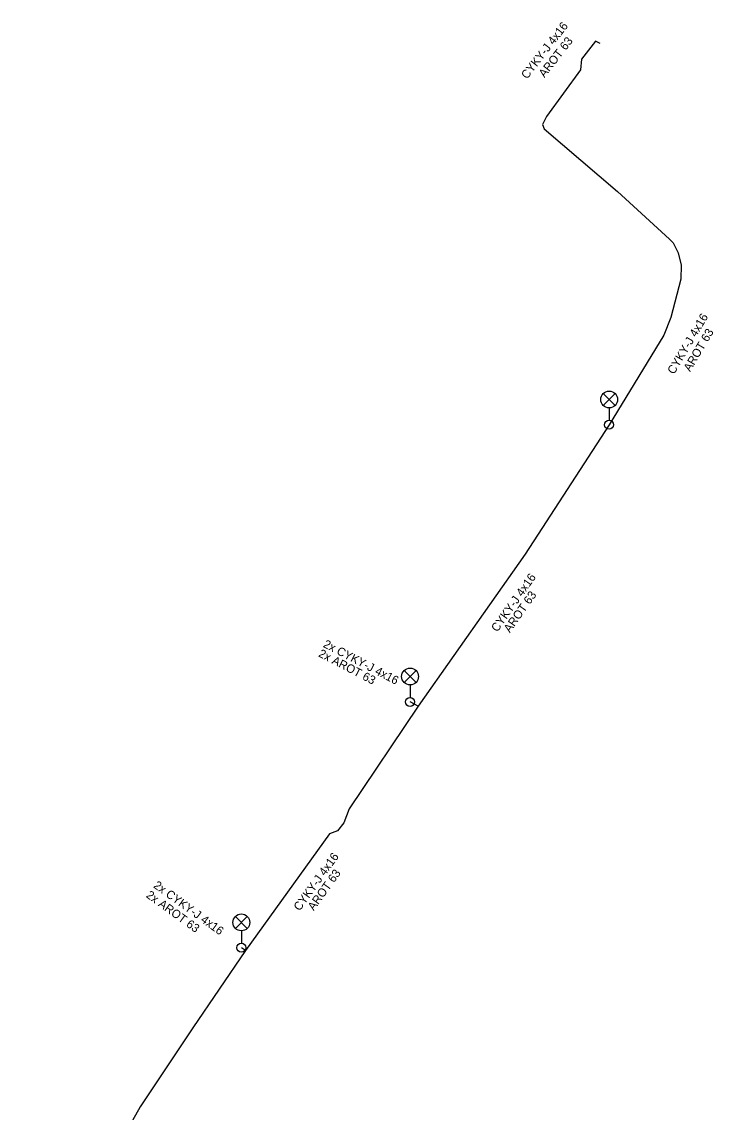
# Model space of a CAD drawing. Extents: x -600499 to -600324, y -1203856 to -1203661.
# Drawn here: x -600385.3 to -600323.8, y -1203757.5 to -1203660.6 of the extents above; entities that cross this region are included whole.
import ezdxf

# ---------------------------------------------------------------- set-up
doc = ezdxf.new("R2010")
doc.units = 0
for name, color, linetype in [('CIZÍ_PODZEM', 7, 'Continuous'), ('Default', 7, 'Continuous'), ('Vrstva 13', 7, 'Continuous'), ('Vrstva 5', 7, 'Continuous'), ('Vrstva 6', 7, 'Continuous'), ('ZP_EON', 7, 'Continuous')]:
    doc.layers.add(name, color=color, linetype=linetype)

# ---------------------------------------------------------------- blocks, each defined once
blk = doc.blocks.new('6.560')
at = {"layer": 'ZP_EON'}
for p, q in [((-0.53, 1.72), (0.53, 2.78)), ((-0.53, 2.78), (0.53, 1.72)), ((0, 1.5), (0, 0.4))]:
    blk.add_line(p, q, dxfattribs=at)
for centre, radius in [((0, 2.25), 0.75), ((0, 0), 0.4)]:
    blk.add_circle(centre, radius, dxfattribs=at)

msp = doc.modelspace()

# ---------------------------------------------------------------- linework, layer by layer
at = {"layer": 'Vrstva 13'}
for p, q in [((-600350.09, -1203721.39), (-600350.8, -1203721.02)), ((-600365.44, -1203743.11), (-600365.8, -1203742.86))]:
    msp.add_line(p, q, dxfattribs=at)
for points in [[(-600333.91, -1203662.54), (-600334.31, -1203662.32), (-600335.56, -1203663.93), (-600335.66, -1203664.87), (-600338.68, -1203669.03), (-600339.03, -1203669.74), (-600338.89, -1203670.11), (-600332.36, -1203675.7), (-600327.72, -1203679.92), (-600327.42, -1203680.26), (-600326.96, -1203681.14), (-600326.7, -1203682.24), (-600326.74, -1203683.47), (-600327.61, -1203686.88), (-600328.25, -1203688.44), (-600333.1, -1203696.41)], [(-600333.1, -1203696.41), (-600340.56, -1203707.89), (-600350.09, -1203721.39)], [(-600350.09, -1203721.39), (-600356.21, -1203730.52), (-600356.7, -1203731.78), (-600357.24, -1203732.48), (-600357.96, -1203732.75), (-600365.44, -1203743.11)], [(-600365.44, -1203743.11), (-600370.1, -1203749.97), (-600374.79, -1203756.99), (-600385.32, -1203775.71)]]:
    msp.add_lwpolyline(points, dxfattribs=at)
at = {"layer": 'Vrstva 5'}
for p, q in [((-600350.09, -1203721.39), (-600350.8, -1203721.02)), ((-600365.44, -1203743.11), (-600365.8, -1203742.86))]:
    msp.add_line(p, q, dxfattribs=at)
for points in [[(-600333.91, -1203662.54), (-600334.31, -1203662.32), (-600335.56, -1203663.93), (-600335.66, -1203664.87), (-600338.68, -1203669.03), (-600339.03, -1203669.74), (-600338.89, -1203670.11), (-600332.36, -1203675.7), (-600327.72, -1203679.92), (-600327.42, -1203680.26), (-600326.96, -1203681.14), (-600326.7, -1203682.24), (-600326.74, -1203683.47), (-600327.61, -1203686.88), (-600328.25, -1203688.44), (-600333.1, -1203696.41)], [(-600333.1, -1203696.41), (-600340.56, -1203707.89), (-600350.09, -1203721.39)], [(-600350.09, -1203721.39), (-600356.21, -1203730.52), (-600356.7, -1203731.78), (-600357.24, -1203732.48), (-600357.96, -1203732.75), (-600365.44, -1203743.11)], [(-600365.44, -1203743.11), (-600370.1, -1203749.97), (-600374.79, -1203756.99), (-600385.32, -1203775.71)]]:
    msp.add_lwpolyline(points, dxfattribs=at)

# ---------------------------------------------------------------- block references
at = {"layer": 'Default'}
for p in [(-600333.1, -1203696.41), (-600350.8, -1203721.02), (-600365.8, -1203742.86)]:
    msp.add_blockref('6.560', p, dxfattribs=at)

# ---------------------------------------------------------------- texts
at = {"layer": 'CIZÍ_PODZEM'}
for s, rotation, p in [('AROT 63', 52.17432, (-600338.843, -1203665.621)), ('AROT 63', 59.37, (-600325.901, -1203691.743)), ('AROT 63', 54.78074, (-600341.927, -1203714.929)), ('2x AROT 63', 332.47477, (-600359.009, -1203716.959)), ('AROT 63', 54.17042, (-600359.361, -1203739.62)), ('2x AROT 63', 324.05789, (-600374.331, -1203738.327))]:
    msp.add_text(s, height=0.75, rotation=rotation, dxfattribs=at).set_placement(p)
at = {"layer": 'Vrstva 6'}
for s, rotation, p in [('CYKY-J 4x16', 52.17432, (-600340.4, -1203665.752)), ('CYKY-J 4x16', 59.37, (-600327.33, -1203691.982)), ('CYKY-J 4x16', 54.78074, (-600343.041, -1203714.868)), ('2x CYKY-J 4x16', 332.47477, (-600358.584, -1203716.118)), ('CYKY-J 4x16', 54.17042, (-600360.615, -1203739.65)), ('2x CYKY-J 4x16', 324.05789, (-600373.675, -1203737.465))]:
    msp.add_text(s, height=0.75, rotation=rotation, dxfattribs=at).set_placement(p)

doc.saveas('drawing.dxf')
